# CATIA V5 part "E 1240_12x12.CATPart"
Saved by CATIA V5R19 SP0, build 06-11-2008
Definition: E 1240_12x12
Nomenclature: E 1240_12x12
Description: PART-E 1240_12x12-DESC
Material "Steel": density 7860 kg/m3, Young's modulus 2e+11 Pa, Poisson ratio 0.266, thermal expansion 1.17e-05 1/K
Bounding box of the stored display mesh (mm): x -9 to 9, y -9 to 9, z -16 to 21
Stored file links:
  G:\UTB\Kombinované\Bakalářská práce\Catia\FORMA\E 1240_12x12.CATPart
  D:\Aplikace\CATIA\Nová složka\win_b64\startup\materials\Catalog.CATMaterial
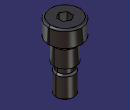
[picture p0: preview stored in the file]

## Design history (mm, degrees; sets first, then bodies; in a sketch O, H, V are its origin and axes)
Body1 "E 1240_12x12" (main body)
  Solid1: solid without history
